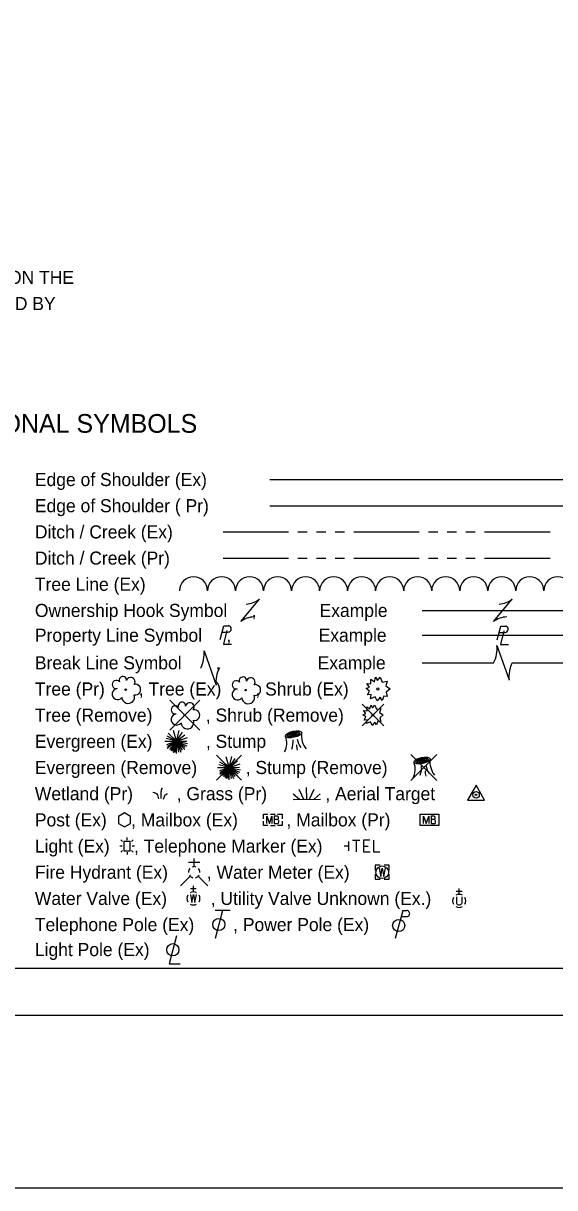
# Model space of a CAD drawing. Extents: x -20.5 to 34, y -66 to 23.9.
# Drawn here: x 7.92 to 13.61, y -1.84 to 10.61 of the extents above; entities that cross this region are included whole.
import ezdxf

# ---------------------------------------------------------------- set-up
doc = ezdxf.new("R2010")
doc.units = 0
for name, color, linetype in [('SH_Border', 7, 'Continuous'), ('SH_Cut_Line', 7, 'Continuous'), ('SH_Text', 7, 'Continuous')]:
    doc.layers.add(name, color=color, linetype=linetype)

msp = doc.modelspace()

# ---------------------------------------------------------------- linework, layer by layer
at = {"layer": 'SH_Border'}
msp.add_lwpolyline([(1.5, 21.5), (33.5, 21.5), (33.5, 0.5), (1.5, 0.5)], close=True, dxfattribs=at)
at = {"layer": 'SH_Cut_Line'}
msp.add_lwpolyline([(0, 0), (34, 0), (34, 22), (0, 22)], close=True, dxfattribs=at)
at = {"layer": 'SH_Text'}
for p, q in [((10.564, 5.73), (14.047, 5.73)), ((10.564, 5.45), (14.047, 5.45)), ((10.063, 5.17), (10.763, 5.17)), ((10.863, 5.17), (10.963, 5.17)), ((11.063, 5.17), (11.163, 5.17)), ((11.263, 5.17), (11.363, 5.17)), ((11.463, 5.17), (12.163, 5.17)), ((12.263, 5.17), (12.363, 5.17)), ((12.463, 5.17), (12.563, 5.17)), ((12.663, 5.17), (12.763, 5.17)), ((12.863, 5.17), (13.563, 5.17)), ((10.063, 4.89), (10.763, 4.89)), ((10.863, 4.89), (10.963, 4.89)), ((11.063, 4.89), (11.163, 4.89)), ((11.263, 4.89), (11.363, 4.89)), ((11.463, 4.89), (12.163, 4.89)), ((12.263, 4.89), (12.363, 4.89)), ((12.463, 4.89), (12.563, 4.89)), ((12.663, 4.89), (12.763, 4.89)), ((12.863, 4.89), (13.563, 4.89)), ((10.251, 4.21), (10.451, 4.45)), ((12.959, 4.21), (13.159, 4.45)), ((10.351, 4.33), (10.351, 4.33)), ((12.194, 4.33), (13.976, 4.33)), ((13.059, 4.33), (13.059, 4.33)), ((10.051, 4.099), (10.116, 4.099)), ((10.091, 4.068), (10.091, 4.068)), ((12.194, 4.065), (13.976, 4.065)), ((13.017, 4.095), (13.082, 4.095)), ((13.057, 4.064), (13.057, 4.064)), ((9.858, 3.898), (9.988, 3.53)), ((12.994, 3.954), (13.124, 3.586)), ((12.194, 3.77), (12.959, 3.77)), ((13.059, 3.77), (13.059, 3.77)), ((13.159, 3.77), (13.976, 3.77)), ((9.923, 3.714), (9.923, 3.714)), ((9.491, 3.37), (9.812, 3.049)), ((9.812, 3.37), (9.491, 3.049)), ((11.55, 3.326), (11.782, 3.094)), ((11.782, 3.326), (11.55, 3.094)), ((9.652, 3.21), (9.652, 3.21)), ((11.666, 3.21), (11.666, 3.21)), ((9.562, 2.93), (9.475, 3.017)), ((9.562, 2.93), (9.531, 3.045)), ((9.562, 2.93), (9.593, 3.047)), ((9.562, 2.93), (9.628, 3.027)), ((9.562, 2.93), (9.653, 3)), ((9.439, 2.93), (9.562, 2.93)), ((9.562, 2.93), (9.452, 2.959)), ((9.562, 2.93), (9.455, 2.891)), ((9.562, 2.93), (9.462, 2.873)), ((9.562, 2.93), (9.464, 2.987)), ((9.562, 2.93), (9.464, 2.855)), ((9.562, 2.93), (9.488, 2.843)), ((9.562, 2.93), (9.504, 2.829)), ((9.562, 2.93), (9.52, 2.821)), ((9.562, 2.93), (9.53, 2.808)), ((9.562, 2.93), (9.549, 2.815)), ((9.562, 2.93), (9.68, 2.97)), ((9.562, 2.93), (9.675, 2.932)), ((9.562, 2.799), (9.562, 2.93)), ((9.562, 2.93), (9.585, 2.814)), ((9.562, 2.93), (9.61, 2.813)), ((9.562, 2.93), (9.625, 2.835)), ((9.562, 2.93), (9.652, 2.842)), ((9.562, 2.93), (9.658, 2.866)), ((9.562, 2.93), (9.674, 2.881)), ((9.562, 2.93), (9.683, 2.906)), ((10.836, 2.93), (10.836, 2.93)), ((9.992, 2.783), (10.26, 2.516)), ((10.26, 2.783), (9.992, 2.516)), ((10.126, 2.65), (10.095, 2.765)), ((10.126, 2.65), (10.157, 2.767)), ((10.126, 2.65), (10.192, 2.747)), ((12.072, 2.789), (12.35, 2.511)), ((12.35, 2.789), (12.072, 2.511)), ((10.003, 2.65), (10.126, 2.65)), ((10.126, 2.65), (10.016, 2.679)), ((10.126, 2.65), (10.019, 2.611)), ((10.126, 2.65), (10.026, 2.593)), ((10.126, 2.65), (10.028, 2.707)), ((10.126, 2.65), (10.028, 2.575)), ((10.126, 2.65), (10.039, 2.737)), ((10.126, 2.65), (10.052, 2.563)), ((10.126, 2.65), (10.068, 2.549)), ((10.126, 2.65), (10.084, 2.541)), ((10.126, 2.65), (10.094, 2.528)), ((10.126, 2.65), (10.113, 2.535)), ((10.126, 2.65), (10.217, 2.72)), ((10.126, 2.65), (10.244, 2.69)), ((10.126, 2.65), (10.239, 2.652)), ((10.126, 2.519), (10.126, 2.65)), ((10.126, 2.65), (10.149, 2.534)), ((10.126, 2.65), (10.174, 2.533)), ((10.126, 2.65), (10.189, 2.555)), ((10.126, 2.65), (10.216, 2.562)), ((10.126, 2.65), (10.222, 2.586)), ((10.126, 2.65), (10.238, 2.601)), ((10.126, 2.65), (10.247, 2.626)), ((10.126, 2.65), (10.126, 2.65)), ((12.211, 2.65), (12.211, 2.65)), ((12.211, 2.65), (12.211, 2.65)), ((10.928, 2.309), (10.876, 2.415)), ((10.958, 2.31), (10.956, 2.435)), ((10.988, 2.31), (11.037, 2.418)), ((11.036, 2.311), (11.103, 2.37)), ((10.879, 2.309), (10.811, 2.366)), ((10.812, 2.308), (11.104, 2.312)), ((10.569, 2.151), (10.619, 2.151)), ((10.569, 2.029), (10.619, 2.029)), ((10.594, 2.09), (10.594, 2.09)), ((12.273, 2.09), (12.273, 2.09)), ((8.987, 1.858), (8.968, 1.877)), ((9.035, 1.874), (9.035, 1.9)), ((9.101, 1.877), (9.083, 1.858)), ((8.983, 1.81), (8.956, 1.81)), ((8.987, 1.761), (8.968, 1.743)), ((9.035, 1.81), (9.035, 1.81)), ((9.035, 1.746), (9.035, 1.719)), ((9.101, 1.743), (9.083, 1.761)), ((9.114, 1.81), (9.087, 1.81)), ((11.407, 1.81), (11.358, 1.81)), ((11.407, 1.76), (11.407, 1.86)), ((9.813, 1.633), (9.693, 1.633)), ((9.753, 1.59), (9.753, 1.676)), ((9.753, 1.53), (9.753, 1.53)), ((9.753, 1.53), (9.753, 1.53)), ((11.766, 1.53), (11.766, 1.53)), ((9.711, 1.487), (9.607, 1.383)), ((9.744, 1.32), (9.744, 1.383)), ((9.795, 1.487), (9.899, 1.383)), ((9.775, 1.352), (9.712, 1.352)), ((9.744, 1.25), (9.744, 1.25)), ((12.622, 1.325), (12.558, 1.325)), ((12.563, 1.266), (12.563, 1.198)), ((12.59, 1.293), (12.59, 1.357)), ((12.617, 1.266), (12.617, 1.198)), ((12.59, 1.223), (12.59, 1.223)), ((10.057, 1.12), (9.976, 0.82)), ((10.137, 1.12), (9.977, 1.12)), ((11.986, 1.12), (11.905, 0.82)), ((11.969, 1.056), (12.028, 1.056)), ((11.986, 1.12), (12.028, 1.12)), ((-19.829, -1.844), (14.969, -1.844))]:
    msp.add_line(p, q, dxfattribs=at)
for points in [[(10.03, 4.019), (10.069, 4.167), (10.121, 4.167)], [(10.104, 4.116), (10.065, 3.968), (10.152, 3.968)], [(12.996, 4.015), (13.035, 4.163), (13.086, 4.163)], [(13.07, 4.112), (13.031, 3.964), (13.118, 3.964)], [(11.715, 3.58), (11.745, 3.617), (11.766, 3.564), (11.82, 3.573), (11.804, 3.523), (11.851, 3.493), (11.808, 3.456), (11.82, 3.411), (11.783, 3.414), (11.767, 3.368), (11.745, 3.403), (11.711, 3.362), (11.69, 3.406), (11.639, 3.385), (11.648, 3.432), (11.608, 3.428), (11.631, 3.467), (11.593, 3.496), (11.63, 3.509), (11.6, 3.549), (11.646, 3.544), (11.645, 3.596), (11.682, 3.567), (11.693, 3.616), (11.715, 3.58)], [(11.663, 3.287), (11.688, 3.318), (11.706, 3.273), (11.752, 3.281), (11.738, 3.238), (11.778, 3.213), (11.742, 3.181), (11.752, 3.142), (11.72, 3.145), (11.706, 3.107), (11.688, 3.136), (11.659, 3.101), (11.641, 3.139), (11.598, 3.121), (11.606, 3.161), (11.572, 3.157), (11.592, 3.191), (11.559, 3.215), (11.59, 3.226), (11.565, 3.26), (11.604, 3.256), (11.603, 3.3), (11.635, 3.276), (11.644, 3.317), (11.663, 3.287)], [(8.942, 2.052), (9.006, 2.015), (9.071, 2.052), (9.071, 2.127), (9.006, 2.165), (8.942, 2.127), (8.942, 2.052)], [(10.494, 2.102), (10.494, 2.151), (10.543, 2.151)], [(10.53, 2.05), (10.53, 2.13), (10.559, 2.05), (10.586, 2.13), (10.586, 2.05)], [(10.646, 2.093), (10.649, 2.096), (10.651, 2.098), (10.652, 2.1), (10.652, 2.101), (10.654, 2.104), (10.654, 2.106), (10.656, 2.11), (10.656, 2.112), (10.656, 2.115), (10.655, 2.118), (10.654, 2.122), (10.652, 2.124), (10.649, 2.127), (10.646, 2.128), (10.645, 2.129), (10.642, 2.13), (10.611, 2.13), (10.611, 2.05), (10.646, 2.05), (10.65, 2.052), (10.654, 2.055), (10.657, 2.06), (10.659, 2.066), (10.659, 2.072), (10.659, 2.076), (10.658, 2.079), (10.656, 2.085), (10.652, 2.089), (10.646, 2.093), (10.611, 2.093)], [(10.645, 2.151), (10.694, 2.151), (10.694, 2.102)], [(12.208, 2.05), (12.208, 2.13), (12.237, 2.05), (12.264, 2.13), (12.264, 2.05)], [(12.324, 2.093), (12.327, 2.096), (12.329, 2.098), (12.33, 2.1), (12.331, 2.101), (12.332, 2.104), (12.332, 2.106), (12.334, 2.11), (12.334, 2.112), (12.334, 2.115), (12.333, 2.118), (12.332, 2.122), (12.33, 2.124), (12.327, 2.127), (12.324, 2.128), (12.323, 2.129), (12.32, 2.13), (12.289, 2.13), (12.289, 2.05), (12.324, 2.05), (12.328, 2.052), (12.332, 2.055), (12.335, 2.06), (12.337, 2.066), (12.337, 2.072), (12.337, 2.076), (12.336, 2.079), (12.334, 2.085), (12.331, 2.089), (12.324, 2.093), (12.289, 2.093)], [(10.543, 2.029), (10.494, 2.029), (10.494, 2.077)], [(10.694, 2.077), (10.694, 2.029), (10.645, 2.029)], [(11.448, 1.872), (11.526, 1.872)], [(11.488, 1.872), (11.488, 1.747)], [(11.633, 1.872), (11.565, 1.872), (11.565, 1.747), (11.638, 1.747)], [(11.673, 1.872), (11.673, 1.747), (11.741, 1.747)], [(11.565, 1.81), (11.614, 1.81)], [(11.746, 1.605), (11.691, 1.605), (11.691, 1.55)], [(11.691, 1.51), (11.691, 1.455), (11.746, 1.455)], [(11.733, 1.575), (11.75, 1.485), (11.766, 1.575), (11.783, 1.485), (11.8, 1.575)], [(11.841, 1.55), (11.841, 1.605), (11.786, 1.605)], [(11.786, 1.455), (11.841, 1.455), (11.841, 1.51)], [(9.712, 1.291), (9.728, 1.205), (9.744, 1.291), (9.76, 1.205), (9.776, 1.291)], [(9.564, 0.849), (9.485, 0.549), (9.603, 0.549)]]:
    msp.add_lwpolyline(points, dxfattribs=at)
for points in [[(12.681, 2.3), (12.861, 2.3), (12.771, 2.461)], [(12.173, 2.151), (12.373, 2.151), (12.373, 2.029), (12.173, 2.029)], [(9.001, 1.76), (9.068, 1.76), (9.068, 1.86), (9.001, 1.86)]]:
    msp.add_lwpolyline(points, close=True, dxfattribs=at)
for centre, radius in [((9.019, 3.482), 0.0084), ((11.719, 3.49), 0.0115), ((10.303, 3.478), 0.0072), ((9.652, 3.21), 0.0072), ((11.666, 3.21), 0.00979), ((12.771, 2.358), 0.035), ((12.771, 2.358), 0.008), ((11.766, 1.53), 0.0675), ((10.017, 0.97), 0.065), ((11.943, 0.96), 0.065), ((9.525, 0.701), 0.065)]:
    msp.add_circle(centre, radius, dxfattribs=at)
for centre, radius, start, end in [((9.746, 4.54), 0.15, 0.0098, 179.9926), ((10.046, 4.54), 0.15, 0.0098, 179.9926), ((10.346, 4.54), 0.15, 0.0098, 179.9926), ((10.646, 4.54), 0.15, 0.0098, 179.9926), ((10.946, 4.54), 0.15, 0.0098, 179.9926), ((11.246, 4.54), 0.15, 0.0098, 179.9926), ((11.546, 4.54), 0.15, 0.0098, 179.9926), ((11.846, 4.54), 0.15, 0.0098, 179.9926), ((12.146, 4.54), 0.15, 0.0098, 179.9926), ((12.446, 4.54), 0.15, 0.0098, 179.9926), ((12.746, 4.54), 0.15, 0.0098, 179.9926), ((13.046, 4.54), 0.15, 0.0098, 179.9926), ((13.346, 4.54), 0.15, 0.0098, 179.9926), ((13.646, 4.54), 0.15, 0.0098, 179.9926), ((10.293, 4.665), 0.267, 273.6945, 306.337), ((13.001, 4.665), 0.267, 273.6945, 306.337), ((10.409, 3.995), 0.267, 93.6945, 126.337), ((13.117, 3.995), 0.267, 93.6945, 126.337), ((10.116, 4.133), 0.0345, 270.471, 81.3281), ((13.081, 4.129), 0.0345, 270.471, 81.3281), ((9.526, 3.866), 0.334, 332.9422, 5.5848), ((12.662, 3.922), 0.334, 332.9422, 5.5848), ((13.456, 3.618), 0.334, 152.9422, 185.5848), ((8.989, 3.583), 0.0395, 354.0047, 205.9741), ((9.073, 3.567), 0.0466, 323.83, 165.0376), ((10.32, 3.563), 0.334, 152.9422, 185.5848), ((10.274, 3.579), 0.0395, 354.0047, 205.9741), ((8.933, 3.435), 0.0592, 96.1722, 320.5737), ((8.919, 3.538), 0.0441, 39.0625, 279.5412), ((9.122, 3.483), 0.0574, 259.1453, 101.4596), ((10.218, 3.432), 0.0592, 96.1722, 320.5737), ((10.204, 3.534), 0.0441, 39.0625, 279.5412), ((10.358, 3.563), 0.0466, 323.83, 165.0376), ((10.407, 3.479), 0.0574, 259.1453, 101.4596), ((9.047, 3.404), 0.0685, 184.9476, 19.4572), ((10.332, 3.4), 0.0685, 184.9476, 19.4572), ((9.552, 3.266), 0.0441, 39.0625, 279.5412), ((9.622, 3.311), 0.0395, 354.0047, 205.9741), ((9.706, 3.295), 0.0466, 323.83, 165.0376), ((9.755, 3.211), 0.0574, 259.1453, 101.4596), ((9.566, 3.163), 0.0592, 96.1722, 320.5737), ((9.68, 3.132), 0.0685, 184.9476, 19.4572), ((11.116, 2.987), 0.215, 171.4106, 219.9194), ((10.544, 2.912), 0.2, 331.5338, 20.9269), ((10.56, 2.931), 0.253, 340.7938, 3.5481), ((11.031, 2.89), 0.182, 178.7926, 197.1224), ((11.161, 3.033), 0.316, 194.9653, 212.1216), ((11.92, 2.632), 0.2, 331.5338, 20.9269), ((11.935, 2.651), 0.253, 340.7938, 3.5481), ((12.537, 2.753), 0.316, 194.9653, 212.1216), ((12.492, 2.707), 0.215, 171.4106, 219.9194), ((12.407, 2.61), 0.182, 178.7926, 197.1224), ((9.753, 1.53), 0.06, 140.021, 184.0629), ((9.753, 1.53), 0.06, 211.8788, 255.8479), ((9.753, 1.53), 0.06, 68.1395, 112.038), ((9.753, 1.53), 0.06, 283.8239, 329.9097), ((9.753, 1.53), 0.06, 356.0165, 39.9889), ((9.744, 1.25), 0.07, 150.0184, 209.9816), ((9.744, 1.25), 0.07, 60.0184, 120.0157), ((9.744, 1.25), 0.07, 330.0184, 29.9816), ((12.59, 1.223), 0.07, 150.0184, 209.9816), ((12.59, 1.223), 0.07, 60.0184, 120.0157), ((12.59, 1.223), 0.07, 330.0184, 29.9816), ((9.744, 1.25), 0.07, 239.9843, 299.9816), ((12.59, 1.223), 0.07, 239.9843, 299.9816), ((12.59, 1.21), 0.03, 205.1924, 334.8076), ((12.029, 1.088), 0.0319, 268.8767, 91.1233)]:
    msp.add_arc(centre, radius, start, end, dxfattribs=at)
for centre, major_axis in [((10.817, 3.005), (0.0868, 0.0187)), ((10.817, 3.005), (0.0651, 0.0141)), ((10.817, 3.005), (0.0488, 0.0105)), ((10.817, 3.005), (0.0275, 0.0059)), ((10.817, 3.005), (0.0154, 0.0033)), ((12.193, 2.725), (0.0868, 0.0187)), ((12.193, 2.725), (0.0651, 0.0141)), ((12.193, 2.725), (0.0488, 0.0105)), ((12.193, 2.725), (0.0275, 0.0059)), ((12.193, 2.725), (0.0154, 0.0033))]:
    msp.add_ellipse(centre, major_axis=major_axis, ratio=0.36865, dxfattribs=at)
for points in [[(9.311, 2.385), (9.352, 2.368), (9.37, 2.314)], [(9.398, 2.318), (9.398, 2.366), (9.404, 2.41), (9.413, 2.431)], [(9.426, 2.311), (9.438, 2.35), (9.467, 2.373)]]:
    msp.add_spline(points, degree=3, dxfattribs=at)

# ---------------------------------------------------------------- texts
for s, height, p in [('THE LOCATION OF THE UNDERGROUND UTILITIES SHOWN ON THE ', 0.14, (2.34, 7.822)), ('PLANS ARE AS OBTAINED FROM THE OWNERS AS REQUIRED BY ', 0.14, (2.34, 7.542)), ('CONVENTIONAL SYMBOLS', 0.2, (6.308, 6.23)), ('Edge of Shoulder (Ex)', 0.14, (8.047, 5.66)), ('Edge of Shoulder ( Pr)', 0.14, (8.047, 5.38)), ('Ditch / Creek (Ex)', 0.14, (8.047, 5.1)), ('Ditch / Creek (Pr)', 0.14, (8.047, 4.82)), ('Tree Line (Ex)', 0.14, (8.047, 4.54)), ('Ownership Hook Symbol     ,             Example', 0.14, (8.047, 4.26)), ('Property Line Symbol     ,                  Example', 0.14, (8.047, 3.995)), ('Break Line Symbol       ,                    Example', 0.14, (8.047, 3.7)), ('Tree (Pr)       , Tree (Ex)       , Shrub (Ex)', 0.14, (8.047, 3.42)), ('Tree (Remove)           , Shrub (Remove)', 0.14, (8.047, 3.14)), ('Evergreen (Ex)           , Stump ', 0.14, (8.047, 2.86)), ('Evergreen (Remove)          , Stump (Remove)', 0.14, (8.047, 2.58)), ('Wetland (Pr)         , Grass (Pr)            , Aerial Target    ', 0.14, (8.047, 2.3)), ('Post (Ex)     , Mailbox (Ex)          , Mailbox (Pr)', 0.14, (8.047, 2.02)), ('Light (Ex)     , Telephone Marker (Ex)     ', 0.14, (8.047, 1.74)), ('Fire Hydrant (Ex)        , Water Meter (Ex)', 0.14, (8.047, 1.46)), ('Water Valve (Ex)         , Utility Valve Unknown (Ex.)', 0.14, (8.047, 1.18)), ('Telephone Pole (Ex)        , Power Pole (Ex)', 0.14, (8.047, 0.9)), ('Light Pole (Ex)     ', 0.14, (8.047, 0.633))]:
    msp.add_text(s, height=height, dxfattribs=at).set_placement(p)

doc.saveas('drawing.dxf')
